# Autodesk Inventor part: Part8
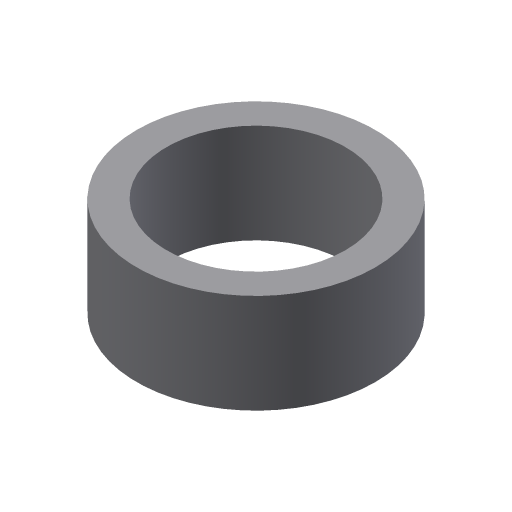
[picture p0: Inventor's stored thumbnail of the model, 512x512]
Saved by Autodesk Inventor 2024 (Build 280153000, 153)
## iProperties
Shininess: 77.0
Length Units: 11269
Angle Units: 11279
Time Units: 11290
Mass Units: 11283
Length Display Precision: 3
Angle Display Precision: 2
Created: 2002-01
Part Number: Part8
Document SubType Name: Modeling
Designer: ***
Density: 1 g/cm^3
Material: Generic
Appearance: Default
Density: 0.0
Volumn: 0.0
Area: 0.0
PropertySet Name: Model Information
Control State: 0
Master: False
Checked Out: False
Author: ***
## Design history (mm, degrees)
sketch "Sketch1"
  geometry: C1 r 30 at (0, 0); C2 r 22.5 at (0, 0)
  constraints: 2 centre point, 1 coincident
  dimensions: "d0" = 60 diameter of C1; "d1" = 45 diameter of C2
extrude "Extrusion1" new body sketch "Sketch1" distance "d2" = 25; taper "d3" = 0 deg
body "Solid1"
